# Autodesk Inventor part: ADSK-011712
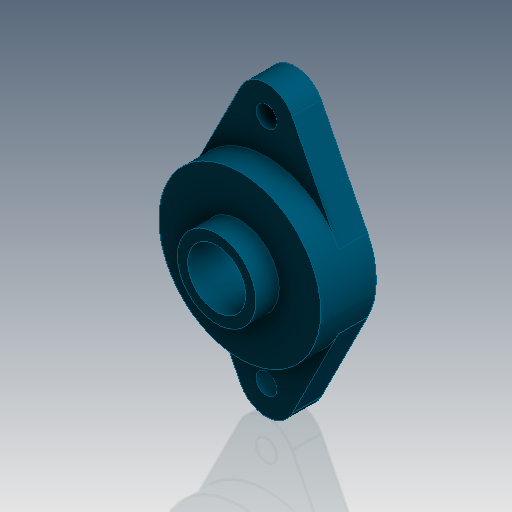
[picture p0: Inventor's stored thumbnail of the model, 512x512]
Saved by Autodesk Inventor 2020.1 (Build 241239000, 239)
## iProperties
Created: 1999-11
Part Number: ADSK-011712
Description: BEARING,FLANGE,1.00,2-BOLT
Document SubType Name: Modeling
Designer: cmcgourin
Material: Acier doux
Density: 7.86 g/cm^3
Appearance: Bearing Blue
Mass: 838.561 g
Surface Area: 209.385 cm^2
Volume: 106.687 cm^3
Control State: 0
Checked Out: False
Master: False
Shininess: 60.0
Length Units: 11269
Angle Units: 11279
Time Units: 11290
Mass Units: 11283
Length Display Precision: 3
Angle Display Precision: 2
Compacted: True
Dimensions: 125x34x70 mm
Mass: 0,839 kg
VLT_Material: Acier doux
DocNumber: ADSK-011712.ipt
Folder: 01 - Themengebiete\Simplification\01 - Packaging machine\
VDS_Category: 3D Komponenten
Density: 0.0
Volumn: 0.0
Area: 0.0
PropertySet Name: Model Information
Author: cmcgourin
Revision Number: -
Title: BEARING,FLANGE,1.00,2-BOLT
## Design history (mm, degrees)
node "Solide1"
  node "Extrusion1" dims "d8" = 12.5, "d9" = 0
  node "Extrusion2" dims "d10" = 11.5, "d11" = 0
  node "Extrusion3" dims "d13" = 10, "d14" = 0
  node "Hole1" dims "d15" = 25, "d16" = 9.525, "d17" = 6.35, "d18" = 60 deg, "d19" = 19.05, "d20" = 118 deg, "d23" = 6
sketch "Sketch1"
  geometry: L1 (-31.256, -15.75)-(-11.163, -55.625); L2 (31.256, -15.75)-(11.163, -55.625); L3 (11.163, 55.625)-(31.256, 15.75); L4 (-11.163, 55.625)-(-31.256, 15.75); L5 (0, 50)-(0, -50); C1 r 4.5 at (0, 50); C2 r 4.5 at (0, -50); A1 r 35 centre (0, 0) between (-31.256, -15.75) and (31.256, -15.75); A2 r 12.5 centre (0, 50) between (11.163, 55.625) and (-11.163, 55.625); A3 r 12.5 centre (0, -50) between (-11.163, -55.625) and (11.163, -55.625); 1 further point
  constraints: 10 end point, 8 point on circle, 8 tangent, 5 centre point, 2 concentric, 2 equal radius, 2 point on line, 1 coincident, 1 midpoint, 1 parallel, 1 vertical
  dimensions: "d0" = 70 diameter of A1; "d5" = 12.5 radius of A2; "d6" = 9 diameter of C1; "d22" = 100 distance of A3.centre A2.centre
sketch "Sketch2"
  geometry: C1 r 35 at (0, 0); A1 r 35 centre (0, 0) between (31.256, -15.75) and (31.256, 15.75) reference; 3 further points
  constraints: 1 centre point, 1 coincident, 1 concentric, 1 other
sketch "Sketch3"
  geometry: C1 r 17 at (0, 0)
  constraints: 1 centre point
  dimensions: "d12" = 34 diameter of C1
workplane "Work Plane1"
workaxis "Work Axis1"
workaxis "Work Axis2"
workplane "Work Plane4"
node "Corps solides"
node "Corps surfaciques"
sketch "Sketch4"
  geometry: 1 further point
